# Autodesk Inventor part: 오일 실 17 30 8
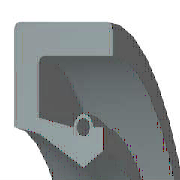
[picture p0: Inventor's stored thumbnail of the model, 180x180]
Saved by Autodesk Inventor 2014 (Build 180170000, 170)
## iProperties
IsCustomPart: 1
Created: 2012-02
Part Number: 오일 실 17 30 8
Material: 고무
Description: 오일-실
Document SubType Name: Modeling
Standard: KS B 2804
Designer: mduedu
Standards Organization: KS
Language: ko-KR
Size Designation: S - 17 30 8
Categories: <MemberInstance><Categories><Category DisplayName="샤프트 부품" InternalName="7f7aeb1f-a693-4053-b835-cee3144e0d98" Mnemonic="SHFT"><Category DisplayName="실링" Intern
Density: 0.93 g/cm^3
Appearance: Rubber - Black - Version 1.1
Author: mduedu
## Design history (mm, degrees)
revolve "본체" stored, may be unused: angle "d17" = 90 deg
revolve "스프링1" stored, may be unused: angle "d18" = 90 deg
body "Solid1"
sketch "스케치1"
  geometry: L1 (0, 15)-(8, 15); L2 (8, 15)-(8, 13.75); L3 (8, 13.75)-(1.75, 13.75); L4 (0, 15)-(0, 10.6); L5 (0, 10.6)-(1.75, 10.25); L6 (1.75, 10.25)-(4.9, 8.5); L7 (4.9, 8.5)-(0, 8.5); L8 (6.3, 9.375)-(6.3, 10.6); L9 (0, 0)-(9.586, 0) reference; L10 (4.9, 8.5)-(6.3, 9.375); L11 (0, 18)-(0, -3) reference; L12 (-1.917, 0)-(11.503, 0) reference; L13 (4.2, 10.6)-(1.75, 11.09); L14 (1.75, 11.09)-(1.75, 13.75); L15 (6.3, 10.6)-(5.6, 10.6); C1 r 0.455 at (4.9, 10.6); A1 r 0.7 centre (4.9, 10.6) between (5.6, 10.6) and (4.2, 10.6)
  constraints: 26 end point, 5 horizontal alignment, 4 perpendicular, 2 centre point, 2 collinear, 2 horizontal, 2 parallel, 2 point on circle, 2 point on line, 2 vertical alignment, 1 coincident
  dimensions: "d0" = 30 diameter of L1 L9 (= SD2); "d1" = 18.75 diameter of L8.start L9 (= ABDM); "d2" = 1.25 distance of L1.end L2.end (computed from SD); "d3" = 0.91 diameter of C1 (= SPDI); "d4" = 1.4 diameter of A1 (= SPDA); "d5" = 17 diameter of L6.end L9 (= NND); "d6" = 20.5 diameter of L5.end L9 (= TKDM); "d7" = 21.2 diameter of L4.end L9 (= HLDM); "d8" = 4.9 distance from line of C1.centre L4 (= SPDST); "d9" = 6.3 distance between parallel lines of L8 L4 (= SDI); "d10" = 8 distance between parallel lines of L2 L4 (= SWDT); "d12" = 1.75 distance between parallel lines of L14 L4 (= SD)
fillet "모깎기1" dims "d11" = 0.5 (= RR)
other parameters: "SD2" = 30 [user parameter; used in 1 equation term], "SWDT" = 8 [user parameter; used in 1 equation term], "RR" = 0.5 [user parameter; used in 1 equation term], "SD" = 1.75 [user parameter; used in 2 equation terms], "NND" = 17 [user parameter; used in 1 equation term], "SPDA" = 1.4 [user parameter; used in 1 equation term], "SPDI" = 0.91 [user parameter; used in 1 equation term], "TKDM" = 20.5 [user parameter; used in 1 equation term], "HLDM" = 21.2 [user parameter; used in 1 equation term], "ABDM" = 18.75 [user parameter; used in 1 equation term], "SDI" = 6.3 [user parameter; used in 1 equation term], "SPDST" = 4.9 [user parameter; used in 1 equation term], "d13" = 0, "d14" = 0, "d15" = 0, "LAB" = 0.35 [user parameter]
